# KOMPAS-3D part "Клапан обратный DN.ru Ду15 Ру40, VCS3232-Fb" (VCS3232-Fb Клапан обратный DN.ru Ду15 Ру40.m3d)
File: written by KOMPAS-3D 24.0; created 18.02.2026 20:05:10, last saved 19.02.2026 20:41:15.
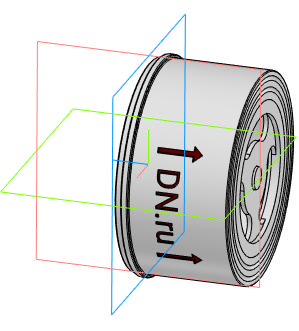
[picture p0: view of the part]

Document properties: Автор: R2D2; Полное имя файла: VCS3232-Fb Клапан обратный DN.ru Ду15 Ру40.cdw

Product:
- Body: Тело 1  | qty 1
    Масса: 0.085135
- Body: Тело 2  | qty 1
    Масса: 0.016987
- Part/product: Клапан обратный DN.ru Ду15 Ру40  | designation VCS3232-Fb
    Масса: 0.17
    Раздел спецификации: Прочие изделия
    Форматы листов документа: A4
    Примечание: D100-03705
    additional columns: 1; D100-03705

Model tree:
1. Операция без истории:17
2. Операция без истории:18

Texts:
  Точка начала. Х
  Точка начала. Y
  Точка начала. Z
  VCS3232-Fb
